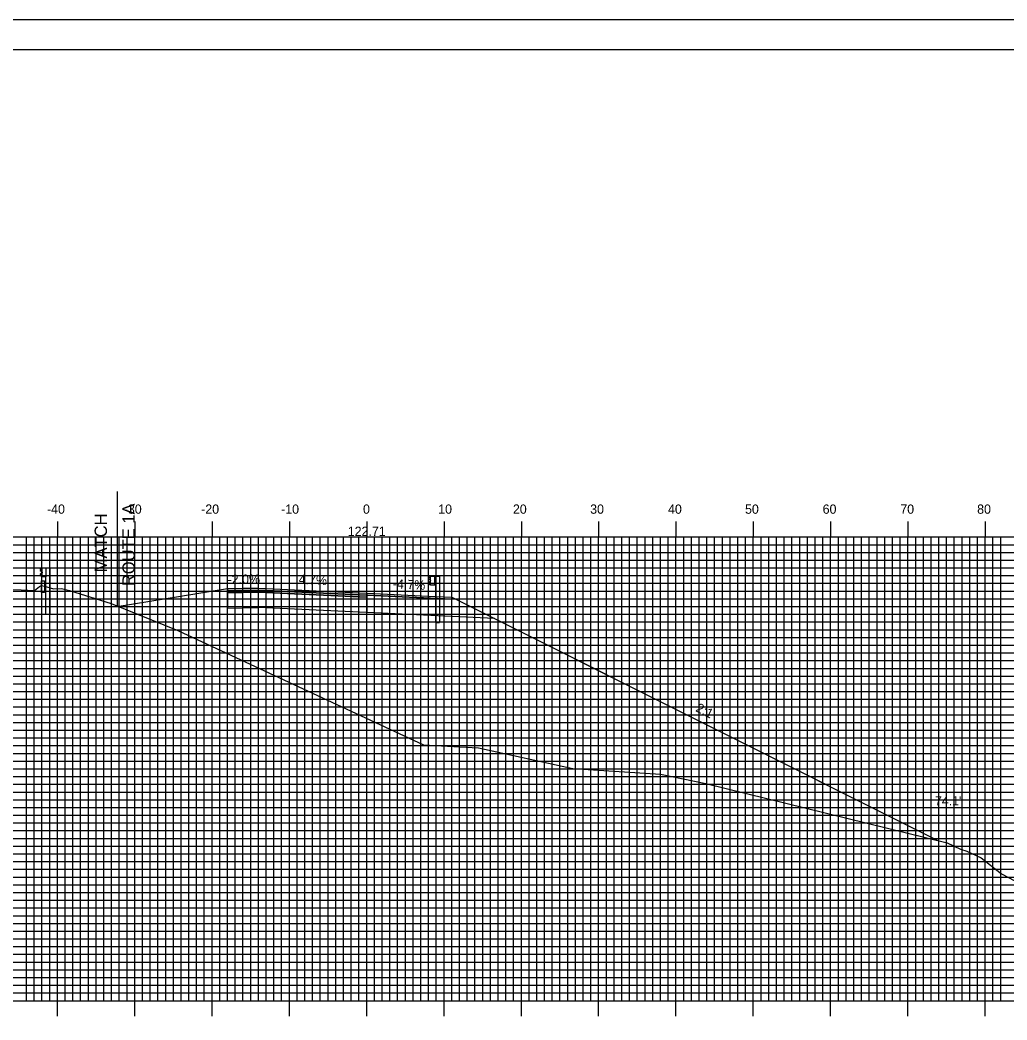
# Model space of a CAD drawing. Extents: x 856871 to 857214, y 364366 to 364586.
# Drawn here: x 856992 to 857119.6, y 364456.3 to 364585.7 of the extents above; entities that cross this region are included whole.
import ezdxf

# ---------------------------------------------------------------- set-up
doc = ezdxf.new("R2010")
doc.units = 0
for name, color, linetype in [('ANNOTATION', 7, 'Continuous'), ('BORDER', 7, 'Continuous'), ('D_Guardrail_Beam_Rt', 7, 'Continuous'), ('D_Roadway_Centerline', 7, 'Continuous'), ('D_Roadway_Centerline_Text', 7, 'Continuous'), ('D_Roadway_Edge_Shoulder', 7, 'Continuous'), ('D_Roadway_Edge_TW', 7, 'Continuous'), ('D_Roadway_Pavement', 7, 'Continuous'), ('D_Roadway_SlopeLines', 7, 'Continuous'), ('D_Roadway_SubGrade', 7, 'Continuous'), ('D_Text_Standard', 7, 'Continuous'), ('H_V ANNOTATION', 7, 'Continuous'), ('MAJOR', 7, 'Continuous'), ('MINOR', 7, 'Continuous'), ('PLOT BOUNDARY', 7, 'Continuous'), ('S_Curb_Type_1', 7, 'Continuous'), ('S_Guardrail_Beam', 7, 'Continuous'), ('S_Roadway_Centerline', 7, 'Continuous')]:
    doc.layers.add(name, color=color, linetype=linetype)

msp = doc.modelspace()

# ---------------------------------------------------------------- linework, layer by layer
at = {"layer": 'BORDER'}
msp.add_lwpolyline([(856887.22, 364371.79), (857207.22, 364371.79), (857207.22, 364581.79), (856887.22, 364581.79)], close=True, dxfattribs=at)
at = {"layer": 'D_Guardrail_Beam_Rt'}
for p, q in [((857045, 364513.6), (857044.86, 364513.5)), ((857045.09, 364513.62), (857045.02, 364513.61)), ((857045.09, 364513.7), (857045.78, 364513.7)), ((857045.09, 364512.54), (857045.09, 364513.7)), ((857045.61, 364513.7), (857045.61, 364512.54)), ((857045.72, 364513.7), (857045.72, 364512.54)), ((857045.78, 364513.7), (857046.25, 364513.7)), ((857045.78, 364513.7), (857045.78, 364512.54)), ((857046.25, 364513.7), (857046.25, 364507.7)), ((857044.86, 364513.36), (857045.06, 364513.22)), ((857045.06, 364513.02), (857044.86, 364512.88)), ((857044.86, 364512.74), (857045, 364512.64)), ((857045.02, 364512.63), (857045.09, 364512.62)), ((857045.09, 364513.16), (857045.09, 364513.09)), ((857045.78, 364512.54), (857045.09, 364512.54)), ((857045.76, 364507.7), (857045.76, 364512.54)), ((857045.76, 364507.7), (857046.25, 364507.7))]:
    msp.add_line(p, q, dxfattribs=at)
for centre, major_axis, start_param, end_param in [((857044.91, 364513.43), (-0.0877, 0), 5.323254, 7.243116), ((857045.03, 364513.56), (-0.0417, 0), 4.907132, 5.323254), ((857044.91, 364512.81), (-0.0877, 0), 5.323254, 7.243116), ((857045.03, 364512.68), (-0.0417, 0), 0.959931, 1.376053), ((857045.01, 364513.16), (0.0789, 0), 0, 0.959931), ((857045.01, 364513.09), (0.0789, 0), 5.323254, 6.283185)]:
    msp.add_ellipse(centre, major_axis=major_axis, ratio=0.995501, start_param=start_param, end_param=end_param, dxfattribs=at)
at = {"layer": 'D_Roadway_Centerline'}
msp.add_lwpolyline([(857018.82, 364512.08), (857022.82, 364512.16), (857036.82, 364511.5), (857044.82, 364511.12), (857047.82, 364510.98), (857053.35, 364508.22), (857110.88, 364479.45)], dxfattribs=at)
at = {"layer": 'D_Roadway_Edge_Shoulder'}
for points in [[(857022.82, 364512.16), (857018.82, 364512.08), (857018.82, 364511.83), (857022.82, 364511.91)], [(857036.82, 364511.5), (857044.82, 364511.12), (857044.82, 364511.12), (857047.82, 364510.98), (857047.82, 364510.73), (857036.82, 364511.25)]]:
    msp.add_lwpolyline(points, close=True, dxfattribs=at)
at = {"layer": 'D_Roadway_Edge_TW'}
msp.add_lwpolyline([(857022.82, 364512.16), (857036.82, 364511.5), (857036.82, 364511.25), (857022.82, 364511.91)], close=True, dxfattribs=at)
at = {"layer": 'D_Roadway_Pavement'}
for points in [[(857022.82, 364511.91), (857018.82, 364511.83), (857018.82, 364511.58), (857022.82, 364511.66)], [(857022.82, 364511.91), (857036.82, 364511.25), (857036.82, 364511), (857022.82, 364511.66)]]:
    msp.add_lwpolyline(points, close=True, dxfattribs=at)
msp.add_lwpolyline([(857036.82, 364511.25), (857036.82, 364511)], dxfattribs=at)
msp.add_lwpolyline([(857036.82, 364511.25), (857036.82, 364511)], dxfattribs=at)
at = {"layer": 'D_Roadway_SlopeLines'}
for points in [[(857018.82, 364512.08), (857004.56, 364509.73)], [(857047.82, 364510.98), (857110.88, 364479.45)]]:
    msp.add_lwpolyline(points, dxfattribs=at)
at = {"layer": 'D_Roadway_SubGrade'}
msp.add_line((857004.56, 364524.68), (857004.56, 364509.73), dxfattribs=at)
for points in [[(857022.82, 364511.66), (857018.82, 364511.58), (857018.82, 364511.83), (857018.82, 364512.08), (857018.82, 364509.58), (857022.82, 364509.66)], [(857022.82, 364511.66), (857036.82, 364511), (857036.82, 364509), (857022.82, 364509.66)], [(857036.82, 364511), (857036.82, 364511.25), (857047.82, 364510.73), (857047.82, 364510.98), (857053.35, 364508.22), (857036.82, 364509)]]:
    msp.add_lwpolyline(points, close=True, dxfattribs=at)
at = {"layer": 'MAJOR'}
for p, q in [((856996.82, 364520.79), (856996.82, 364518.79)), ((857006.82, 364520.79), (857006.82, 364518.79)), ((857016.82, 364520.79), (857016.82, 364518.79)), ((857026.82, 364520.79), (857026.82, 364518.79)), ((857036.82, 364520.79), (857036.82, 364518.79)), ((857046.82, 364520.79), (857046.82, 364518.79)), ((857056.82, 364520.79), (857056.82, 364518.79)), ((857066.82, 364520.79), (857066.82, 364518.79)), ((857076.82, 364520.79), (857076.82, 364518.79)), ((857086.82, 364520.79), (857086.82, 364518.79)), ((857096.82, 364520.79), (857096.82, 364518.79)), ((857106.82, 364520.79), (857106.82, 364518.79)), ((857116.82, 364520.79), (857116.82, 364518.79)), ((856896.82, 364518.79), (857176.82, 364518.79)), ((856896.82, 364518.79), (857176.82, 364518.79)), ((856996.82, 364458.79), (856996.82, 364518.79)), ((857006.82, 364458.79), (857006.82, 364518.79)), ((857016.82, 364458.79), (857016.82, 364518.79)), ((857026.82, 364458.79), (857026.82, 364518.79)), ((857036.82, 364458.79), (857036.82, 364518.79)), ((857046.82, 364458.79), (857046.82, 364518.79)), ((857056.82, 364458.79), (857056.82, 364518.79)), ((857066.82, 364458.79), (857066.82, 364518.79)), ((857076.82, 364458.79), (857076.82, 364518.79)), ((857086.82, 364458.79), (857086.82, 364518.79)), ((857096.82, 364458.79), (857096.82, 364518.79)), ((857106.82, 364458.79), (857106.82, 364518.79)), ((857116.82, 364458.79), (857116.82, 364518.79)), ((856896.82, 364513.79), (857176.82, 364513.79)), ((856896.82, 364508.79), (857176.82, 364508.79)), ((856896.82, 364503.79), (857176.82, 364503.79)), ((856896.82, 364498.79), (857176.82, 364498.79)), ((856896.82, 364493.79), (857176.82, 364493.79)), ((856896.82, 364488.79), (857176.82, 364488.79)), ((856896.82, 364483.79), (857176.82, 364483.79)), ((856896.82, 364478.79), (857176.82, 364478.79)), ((856896.82, 364473.79), (857176.82, 364473.79)), ((856896.82, 364468.79), (857176.82, 364468.79)), ((856896.82, 364463.79), (857176.82, 364463.79)), ((856896.82, 364458.79), (857176.82, 364458.79)), ((856896.82, 364458.79), (857176.82, 364458.79)), ((856996.82, 364456.78), (856996.82, 364458.79)), ((857006.82, 364456.78), (857006.82, 364458.79)), ((857016.82, 364456.78), (857016.82, 364458.79)), ((857026.82, 364456.78), (857026.82, 364458.79)), ((857036.82, 364456.78), (857036.82, 364458.79)), ((857046.82, 364456.78), (857046.82, 364458.79)), ((857056.82, 364456.78), (857056.82, 364458.79)), ((857066.82, 364456.78), (857066.82, 364458.79)), ((857076.82, 364456.78), (857076.82, 364458.79)), ((857086.82, 364456.78), (857086.82, 364458.79)), ((857096.82, 364456.78), (857096.82, 364458.79)), ((857106.82, 364456.78), (857106.82, 364458.79)), ((857116.82, 364456.78), (857116.82, 364458.79))]:
    msp.add_line(p, q, dxfattribs=at)
at = {"layer": 'MINOR'}
for p, q in [((856992.82, 364458.79), (856992.82, 364518.79)), ((856993.82, 364458.79), (856993.82, 364518.79)), ((856994.82, 364458.79), (856994.82, 364518.79)), ((856995.82, 364458.79), (856995.82, 364518.79)), ((856997.82, 364458.79), (856997.82, 364518.79)), ((856998.82, 364458.79), (856998.82, 364518.79)), ((856999.82, 364458.79), (856999.82, 364518.79)), ((857000.82, 364458.79), (857000.82, 364518.79)), ((857001.82, 364458.79), (857001.82, 364518.79)), ((857002.82, 364458.79), (857002.82, 364518.79)), ((857003.82, 364458.79), (857003.82, 364518.79)), ((857004.82, 364458.79), (857004.82, 364518.79)), ((857005.82, 364458.79), (857005.82, 364518.79)), ((857007.82, 364458.79), (857007.82, 364518.79)), ((857008.82, 364458.79), (857008.82, 364518.79)), ((857009.82, 364458.79), (857009.82, 364518.79)), ((857010.82, 364458.79), (857010.82, 364518.79)), ((857011.82, 364458.79), (857011.82, 364518.79)), ((857012.82, 364458.79), (857012.82, 364518.79)), ((857013.82, 364458.79), (857013.82, 364518.79)), ((857014.82, 364458.79), (857014.82, 364518.79)), ((857015.82, 364458.79), (857015.82, 364518.79)), ((857017.82, 364458.79), (857017.82, 364518.79)), ((857018.82, 364458.79), (857018.82, 364518.79)), ((857019.82, 364458.79), (857019.82, 364518.79)), ((857020.82, 364458.79), (857020.82, 364518.79)), ((857021.82, 364458.79), (857021.82, 364518.79)), ((857022.82, 364458.79), (857022.82, 364518.79)), ((857023.82, 364458.79), (857023.82, 364518.79)), ((857024.82, 364458.79), (857024.82, 364518.79)), ((857025.82, 364458.79), (857025.82, 364518.79)), ((857027.82, 364458.79), (857027.82, 364518.79)), ((857028.82, 364458.79), (857028.82, 364518.79)), ((857029.82, 364458.79), (857029.82, 364518.79)), ((857030.82, 364458.79), (857030.82, 364518.79)), ((857031.82, 364458.79), (857031.82, 364518.79)), ((857032.82, 364458.79), (857032.82, 364518.79)), ((857033.82, 364458.79), (857033.82, 364518.79)), ((857034.82, 364458.79), (857034.82, 364518.79)), ((857035.82, 364458.79), (857035.82, 364518.79)), ((857037.82, 364458.79), (857037.82, 364518.79)), ((857038.82, 364458.79), (857038.82, 364518.79)), ((857039.82, 364458.79), (857039.82, 364518.79)), ((857040.82, 364458.79), (857040.82, 364518.79)), ((857041.82, 364458.79), (857041.82, 364518.79)), ((857042.82, 364458.79), (857042.82, 364518.79)), ((857043.82, 364458.79), (857043.82, 364518.79)), ((857044.82, 364458.79), (857044.82, 364518.79)), ((857045.82, 364458.79), (857045.82, 364518.79)), ((857047.82, 364458.79), (857047.82, 364518.79)), ((857048.82, 364458.79), (857048.82, 364518.79)), ((857049.82, 364458.79), (857049.82, 364518.79)), ((857050.82, 364458.79), (857050.82, 364518.79)), ((857051.82, 364458.79), (857051.82, 364518.79)), ((857052.82, 364458.79), (857052.82, 364518.79)), ((857053.82, 364458.79), (857053.82, 364518.79)), ((857054.82, 364458.79), (857054.82, 364518.79)), ((857055.82, 364458.79), (857055.82, 364518.79)), ((857057.82, 364458.79), (857057.82, 364518.79)), ((857058.82, 364458.79), (857058.82, 364518.79)), ((857059.82, 364458.79), (857059.82, 364518.79)), ((857060.82, 364458.79), (857060.82, 364518.79)), ((857061.82, 364458.79), (857061.82, 364518.79)), ((857062.82, 364458.79), (857062.82, 364518.79)), ((857063.82, 364458.79), (857063.82, 364518.79)), ((857064.82, 364458.79), (857064.82, 364518.79)), ((857065.82, 364458.79), (857065.82, 364518.79)), ((857067.82, 364458.79), (857067.82, 364518.79)), ((857068.82, 364458.79), (857068.82, 364518.79)), ((857069.82, 364458.79), (857069.82, 364518.79)), ((857070.82, 364458.79), (857070.82, 364518.79)), ((857071.82, 364458.79), (857071.82, 364518.79)), ((857072.82, 364458.79), (857072.82, 364518.79)), ((857073.82, 364458.79), (857073.82, 364518.79)), ((857074.82, 364458.79), (857074.82, 364518.79)), ((857075.82, 364458.79), (857075.82, 364518.79)), ((857077.82, 364458.79), (857077.82, 364518.79)), ((857078.82, 364458.79), (857078.82, 364518.79)), ((857079.82, 364458.79), (857079.82, 364518.79)), ((857080.82, 364458.79), (857080.82, 364518.79)), ((857081.82, 364458.79), (857081.82, 364518.79)), ((857082.82, 364458.79), (857082.82, 364518.79)), ((857083.82, 364458.79), (857083.82, 364518.79)), ((857084.82, 364458.79), (857084.82, 364518.79)), ((857085.82, 364458.79), (857085.82, 364518.79)), ((857087.82, 364458.79), (857087.82, 364518.79)), ((857088.82, 364458.79), (857088.82, 364518.79)), ((857089.82, 364458.79), (857089.82, 364518.79)), ((857090.82, 364458.79), (857090.82, 364518.79)), ((857091.82, 364458.79), (857091.82, 364518.79)), ((857092.82, 364458.79), (857092.82, 364518.79)), ((857093.82, 364458.79), (857093.82, 364518.79)), ((857094.82, 364458.79), (857094.82, 364518.79)), ((857095.82, 364458.79), (857095.82, 364518.79)), ((857097.82, 364458.79), (857097.82, 364518.79)), ((857098.82, 364458.79), (857098.82, 364518.79)), ((857099.82, 364458.79), (857099.82, 364518.79)), ((857100.82, 364458.79), (857100.82, 364518.79)), ((857101.82, 364458.79), (857101.82, 364518.79)), ((857102.82, 364458.79), (857102.82, 364518.79)), ((857103.82, 364458.79), (857103.82, 364518.79)), ((857104.82, 364458.79), (857104.82, 364518.79)), ((857105.82, 364458.79), (857105.82, 364518.79)), ((857107.82, 364458.79), (857107.82, 364518.79)), ((857108.82, 364458.79), (857108.82, 364518.79)), ((857109.82, 364458.79), (857109.82, 364518.79)), ((857110.82, 364458.79), (857110.82, 364518.79)), ((857111.82, 364458.79), (857111.82, 364518.79)), ((857112.82, 364458.79), (857112.82, 364518.79)), ((857113.82, 364458.79), (857113.82, 364518.79)), ((857114.82, 364458.79), (857114.82, 364518.79)), ((857115.82, 364458.79), (857115.82, 364518.79)), ((857117.82, 364458.79), (857117.82, 364518.79)), ((857118.82, 364458.79), (857118.82, 364518.79)), ((856896.82, 364517.79), (857176.82, 364517.79)), ((856896.82, 364516.79), (857176.82, 364516.79)), ((856896.82, 364515.79), (857176.82, 364515.79)), ((856896.82, 364514.79), (857176.82, 364514.79)), ((856896.82, 364512.79), (857176.82, 364512.79)), ((856896.82, 364511.79), (857176.82, 364511.79)), ((856896.82, 364510.79), (857176.82, 364510.79)), ((856896.82, 364509.79), (857176.82, 364509.79)), ((856896.82, 364507.79), (857176.82, 364507.79)), ((856896.82, 364506.79), (857176.82, 364506.79)), ((856896.82, 364505.79), (857176.82, 364505.79)), ((856896.82, 364504.79), (857176.82, 364504.79)), ((856896.82, 364502.79), (857176.82, 364502.79)), ((856896.82, 364501.79), (857176.82, 364501.79)), ((856896.82, 364500.79), (857176.82, 364500.79)), ((856896.82, 364499.79), (857176.82, 364499.79)), ((856896.82, 364497.79), (857176.82, 364497.79)), ((856896.82, 364496.79), (857176.82, 364496.79)), ((856896.82, 364495.79), (857176.82, 364495.79)), ((856896.82, 364494.79), (857176.82, 364494.79)), ((856896.82, 364492.79), (857176.82, 364492.79)), ((856896.82, 364491.79), (857176.82, 364491.79)), ((856896.82, 364490.79), (857176.82, 364490.79)), ((856896.82, 364489.79), (857176.82, 364489.79)), ((856896.82, 364487.79), (857176.82, 364487.79)), ((856896.82, 364486.79), (857176.82, 364486.79)), ((856896.82, 364485.79), (857176.82, 364485.79)), ((856896.82, 364484.79), (857176.82, 364484.79)), ((856896.82, 364482.79), (857176.82, 364482.79)), ((856896.82, 364481.79), (857176.82, 364481.79)), ((856896.82, 364480.79), (857176.82, 364480.79)), ((856896.82, 364479.79), (857176.82, 364479.79)), ((856896.82, 364477.79), (857176.82, 364477.79)), ((856896.82, 364476.79), (857176.82, 364476.79)), ((856896.82, 364475.79), (857176.82, 364475.79)), ((856896.82, 364474.79), (857176.82, 364474.79)), ((856896.82, 364472.79), (857176.82, 364472.79)), ((856896.82, 364471.79), (857176.82, 364471.79)), ((856896.82, 364470.79), (857176.82, 364470.79)), ((856896.82, 364469.79), (857176.82, 364469.79)), ((856896.82, 364467.79), (857176.82, 364467.79)), ((856896.82, 364466.79), (857176.82, 364466.79)), ((856896.82, 364465.79), (857176.82, 364465.79)), ((856896.82, 364464.79), (857176.82, 364464.79)), ((856896.82, 364462.79), (857176.82, 364462.79)), ((856896.82, 364461.79), (857176.82, 364461.79)), ((856896.82, 364460.79), (857176.82, 364460.79)), ((856896.82, 364459.79), (857176.82, 364459.79))]:
    msp.add_line(p, q, dxfattribs=at)
at = {"layer": 'PLOT BOUNDARY'}
msp.add_lwpolyline([(856871.04, 364365.67), (857211.04, 364365.67), (857211.04, 364585.67), (856871.04, 364585.67)], close=True, dxfattribs=at)
at = {"layer": 'S_Curb_Type_1'}
msp.add_lwpolyline([(856994.75, 364513.09), (856995.16, 364513.09), (856995.16, 364511.59), (856994.75, 364511.59)], close=True, dxfattribs=at)
msp.add_lwpolyline([(856994.75, 364513.09), (856995.16, 364513.09), (856995.16, 364511.59), (856994.75, 364511.59)], close=True, dxfattribs=at)
at = {"layer": 'S_Guardrail_Beam'}
for p, q in [((856994.86, 364514.79), (856995.34, 364514.79)), ((856994.86, 364513.62), (856994.86, 364514.79)), ((856994.86, 364514.79), (856995.34, 364514.79)), ((856994.86, 364513.62), (856994.86, 364514.79)), ((856995.34, 364514.79), (856995.84, 364514.79)), ((856995.34, 364514.79), (856995.34, 364513.62)), ((856995.34, 364514.79), (856995.84, 364514.79)), ((856995.34, 364514.79), (856995.34, 364513.62)), ((856995.84, 364514.79), (856995.84, 364508.79)), ((856995.84, 364514.79), (856995.84, 364508.79)), ((856994.76, 364514.69), (856994.61, 364514.59)), ((856994.76, 364514.69), (856994.61, 364514.59)), ((856994.61, 364514.45), (856994.81, 364514.31)), ((856994.61, 364514.45), (856994.81, 364514.31)), ((856994.81, 364514.09), (856994.61, 364513.96)), ((856994.81, 364514.09), (856994.61, 364513.96)), ((856994.61, 364513.81), (856994.76, 364513.71)), ((856994.61, 364513.81), (856994.76, 364513.71)), ((856994.86, 364514.71), (856994.77, 364514.7)), ((856994.86, 364514.71), (856994.77, 364514.7)), ((856994.77, 364513.71), (856994.86, 364513.69)), ((856994.77, 364513.71), (856994.86, 364513.69)), ((856994.84, 364514.25), (856994.84, 364514.16)), ((856994.84, 364514.25), (856994.84, 364514.16)), ((856995.34, 364513.62), (856994.86, 364513.62)), ((856995.34, 364513.62), (856994.86, 364513.62)), ((856995.34, 364508.79), (856995.34, 364513.62)), ((856995.34, 364508.79), (856995.34, 364513.62)), ((856995.34, 364508.79), (856995.84, 364508.79)), ((856995.34, 364508.79), (856995.84, 364508.79))]:
    msp.add_line(p, q, dxfattribs=at)
for centre, major_axis, start_param, end_param in [((856994.66, 364514.52), (-0.0877, 0), 5.323254, 7.243116), ((856994.66, 364514.52), (-0.0877, 0), 5.323254, 7.243116), ((856994.66, 364513.88), (-0.0877, 0), 5.323254, 7.243116), ((856994.66, 364513.88), (-0.0877, 0), 5.323254, 7.243116), ((856994.78, 364514.66), (-0.0417, 0), 4.886922, 5.323254), ((856994.78, 364514.66), (-0.0417, 0), 4.886922, 5.323254), ((856994.78, 364513.75), (-0.0417, 0), 0.959931, 1.396263), ((856994.78, 364513.75), (-0.0417, 0), 0.959931, 1.396263), ((856994.76, 364514.25), (0.0789, 0), 0, 0.959931), ((856994.76, 364514.25), (0.0789, 0), 0, 0.959931), ((856994.76, 364514.16), (0.0789, 0), 5.323254, 6.283185), ((856994.76, 364514.16), (0.0789, 0), 5.323254, 6.283185)]:
    msp.add_ellipse(centre, major_axis=major_axis, ratio=0.995501, start_param=start_param, end_param=end_param, dxfattribs=at)
at = {"layer": 'S_Roadway_Centerline'}
msp.add_lwpolyline([(856987.16, 364512.08), (856992.11, 364511.94), (856993.86, 364511.88), (856994.52, 364512.36), (856994.75, 364512.51), (856995.14, 364512.4), (856996.3, 364512.09), (856997.36, 364512.14), (856998.39, 364511.87), (857003.76, 364510.17), (857012.39, 364506.68), (857044.16, 364491.9), (857047.26, 364491.72), (857051.3, 364491.49), (857063.46, 364488.83), (857074.82, 364488.11), (857080.69, 364486.88), (857111.9, 364479.2), (857113.61, 364478.4), (857114.44, 364478.15), (857116.28, 364477.26), (857118.94, 364475.22), (857120.65, 364474.3)], dxfattribs=at)

# ---------------------------------------------------------------- texts
at = {"layer": 'ANNOTATION'}
for s, height, rotation, p in [('ROUTE 1A', 1.6, 90, (857006.83, 364512.42)), ('MATCH', 1.6, 90, (857003.23, 364514.22)), ('-2.0%', 1.2, 1.1458, (857018.84, 364512.68)), ('4.7%', 1.2, 357.2868, (857028, 364512.72)), ('-4.7%', 1.2, 357.2868, (857040.18, 364512.14)), ('2:1', 1.2, 333.4349, (857079.28, 364496.28))]:
    msp.add_text(s, height=height, rotation=rotation, dxfattribs=at).set_placement(p)
at = {"layer": 'D_Roadway_Centerline_Text'}
msp.add_text('122.71', height=1.2, dxfattribs=at).set_placement((857034.37, 364518.92))
at = {"layer": 'D_Text_Standard'}
msp.add_text("74.1'", height=1.2, dxfattribs=at).set_placement((857110.31, 364484.05))
at = {"layer": 'H_V ANNOTATION'}
for s, p in [('-40', (856995.47, 364521.79)), ('-30', (857005.4, 364521.79)), ('-20', (857015.41, 364521.79)), ('-10', (857025.75, 364521.79)), ('0', (857036.34, 364521.79)), ('10', (857046.07, 364521.79)), ('20', (857055.73, 364521.79)), ('30', (857065.72, 364521.79)), ('40', (857075.79, 364521.79)), ('50', (857085.75, 364521.79)), ('60', (857095.79, 364521.79)), ('70', (857105.83, 364521.79)), ('80', (857115.77, 364521.79))]:
    msp.add_text(s, height=1.2, dxfattribs=at).set_placement(p)

doc.saveas('drawing.dxf')
